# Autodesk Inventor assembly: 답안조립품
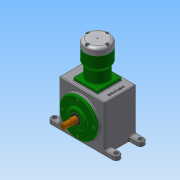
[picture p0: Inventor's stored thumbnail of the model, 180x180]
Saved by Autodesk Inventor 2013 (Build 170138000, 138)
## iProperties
Created: 2016-11
Part Number: 답안조립품
Document SubType Name: Assembly
Designer: Administrator
Mass: 5620.43 g
Surface Area: 4291.87 cm^2
Volume: 1587.82 cm^3
Density: 3.53972 g/cm^3
Author: Administrator
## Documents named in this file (16)
- C:\Users\Administrator\Desktop\361108V1018\답안조립품.iam
- C:\Users\Administrator\Desktop\361108V1018\본체.ipt
- C:\Users\Administrator\Desktop\361108V1018\메인크랭크축.ipt
- C:\Users\Administrator\Desktop\361108V1018\베어링 20 x 47 x 14.ipt
- C:\Users\Administrator\Desktop\361108V1018\베어링 NA 4902.ipt
- C:\Users\Administrator\Desktop\361108V1018\볼트 M4 x 8.ipt
- C:\Users\Administrator\Desktop\361108V1018\볼트 M5 x 20.ipt
- C:\Users\Administrator\Desktop\361108V1018\실린더.ipt
- C:\Users\Administrator\Desktop\361108V1018\실린더헤드.ipt
- C:\Users\Administrator\Desktop\361108V1018\앞커버.ipt
- C:\Users\Administrator\Desktop\361108V1018\오일 실 20 35 8.ipt
- C:\Users\Administrator\Desktop\361108V1018\커넥팅로드.ipt
- C:\Users\Administrator\Desktop\361108V1018\크랭크보조축.ipt
- C:\Users\Administrator\Desktop\361108V1018\피스톤.ipt
- C:\Users\Administrator\Desktop\361108V1018\피스톤핀.ipt
- C:\Users\Administrator\Desktop\361108V1018\가변스프링.ipt
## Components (15 placed, 5 different names)
1. 가변스프링:1
2. ISO 4762 M4 x 8:6
3. ISO 4762 M4 x 8:7
4. ISO 4762 M4 x 8:8
5. ISO 4762 M4 x 8:2
6. 피스톤:1
7. 피스톤핀:1
8. ISO 4762 M4 x 8:1
9. ISO 4762 M4 x 8:3
10. ISO 4762 M4 x 8:4
11. ISO 4762 M4 x 8:5
12. ISO 4762 M5 x 20:1
13. ISO 4762 M5 x 20:2
14. ISO 4762 M5 x 20:3
15. ISO 4762 M5 x 20:4
